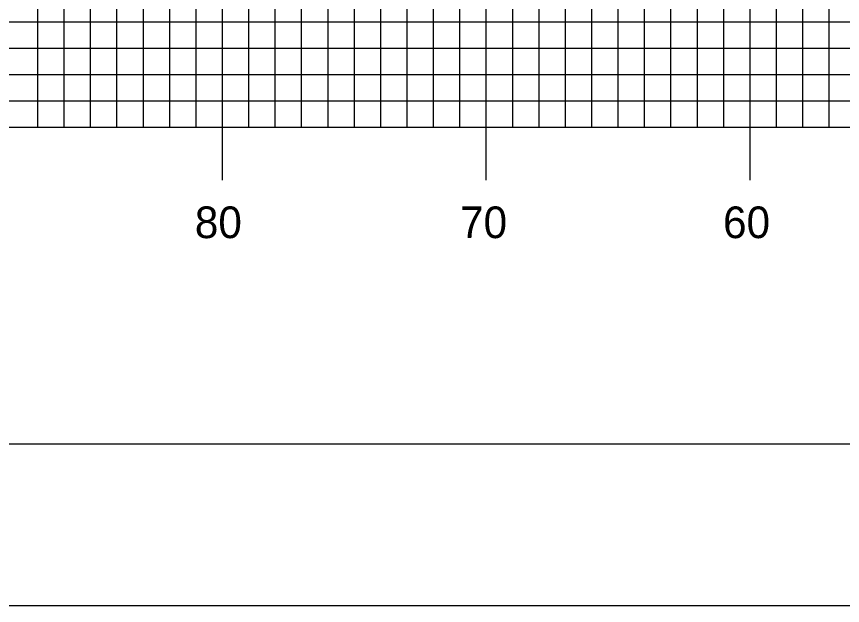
# Model space of a CAD drawing. Extents: x 1757462 to 1757806, y 442591 to 442811.
# Drawn here: x 1757540.3 to 1757571.61, y 442590.55 to 442612.86 of the extents above; entities that cross this region are included whole.
import ezdxf

# ---------------------------------------------------------------- set-up
doc = ezdxf.new("R2010")
doc.units = 0
for name, color, linetype in [('BORDER', 7, 'Continuous'), ('H_V ANNOTATION', 7, 'Continuous'), ('MAJOR', 7, 'Continuous'), ('MINOR', 7, 'Continuous'), ('PLOT BOUNDARY', 7, 'Continuous')]:
    doc.layers.add(name, color=color, linetype=linetype)

msp = doc.modelspace()

# ---------------------------------------------------------------- linework, layer by layer
at = {"layer": 'BORDER'}
msp.add_lwpolyline([(1757478.509, 442596.665), (1757798.509, 442596.665), (1757798.509, 442806.665), (1757478.509, 442806.665)], close=True, dxfattribs=at)
at = {"layer": 'MAJOR'}
for p, q in [((1757548.109, 442608.665), (1757548.109, 442633.665)), ((1757558.109, 442608.665), (1757558.109, 442633.665)), ((1757568.109, 442608.665), (1757568.109, 442633.665)), ((1757488.109, 442608.665), (1757768.109, 442608.665)), ((1757488.109, 442608.665), (1757768.109, 442608.665)), ((1757548.109, 442606.661), (1757548.109, 442608.665)), ((1757558.109, 442606.661), (1757558.109, 442608.665)), ((1757568.109, 442606.661), (1757568.109, 442608.665))]:
    msp.add_line(p, q, dxfattribs=at)
at = {"layer": 'MINOR'}
for p, q in [((1757541.109, 442608.665), (1757541.109, 442633.665)), ((1757542.109, 442608.665), (1757542.109, 442633.665)), ((1757543.109, 442608.665), (1757543.109, 442633.665)), ((1757544.109, 442608.665), (1757544.109, 442633.665)), ((1757545.109, 442608.665), (1757545.109, 442633.665)), ((1757546.109, 442608.665), (1757546.109, 442633.665)), ((1757547.109, 442608.665), (1757547.109, 442633.665)), ((1757549.109, 442608.665), (1757549.109, 442633.665)), ((1757550.109, 442608.665), (1757550.109, 442633.665)), ((1757551.109, 442608.665), (1757551.109, 442633.665)), ((1757552.109, 442608.665), (1757552.109, 442633.665)), ((1757553.109, 442608.665), (1757553.109, 442633.665)), ((1757554.109, 442608.665), (1757554.109, 442633.665)), ((1757555.109, 442608.665), (1757555.109, 442633.665)), ((1757556.109, 442608.665), (1757556.109, 442633.665)), ((1757557.109, 442608.665), (1757557.109, 442633.665)), ((1757559.109, 442608.665), (1757559.109, 442633.665)), ((1757560.109, 442608.665), (1757560.109, 442633.665)), ((1757561.109, 442608.665), (1757561.109, 442633.665)), ((1757562.109, 442608.665), (1757562.109, 442633.665)), ((1757563.109, 442608.665), (1757563.109, 442633.665)), ((1757564.109, 442608.665), (1757564.109, 442633.665)), ((1757565.109, 442608.665), (1757565.109, 442633.665)), ((1757566.109, 442608.665), (1757566.109, 442633.665)), ((1757567.109, 442608.665), (1757567.109, 442633.665)), ((1757569.109, 442608.665), (1757569.109, 442633.665)), ((1757570.109, 442608.665), (1757570.109, 442633.665)), ((1757571.109, 442608.665), (1757571.109, 442633.665)), ((1757488.109, 442612.665), (1757768.109, 442612.665)), ((1757488.109, 442611.665), (1757768.109, 442611.665)), ((1757488.109, 442610.665), (1757768.109, 442610.665)), ((1757488.109, 442609.665), (1757768.109, 442609.665))]:
    msp.add_line(p, q, dxfattribs=at)
at = {"layer": 'PLOT BOUNDARY'}
msp.add_lwpolyline([(1757462.322, 442590.547), (1757802.322, 442590.547), (1757802.322, 442810.547), (1757462.322, 442810.547)], close=True, dxfattribs=at)

# ---------------------------------------------------------------- texts
at = {"layer": 'H_V ANNOTATION'}
for s, p in [('80', (1757547.06, 442604.465)), ('70', (1757557.113, 442604.465)), ('60', (1757567.081, 442604.465))]:
    msp.add_text(s, height=1.2, dxfattribs=at).set_placement(p)

doc.saveas('drawing.dxf')
